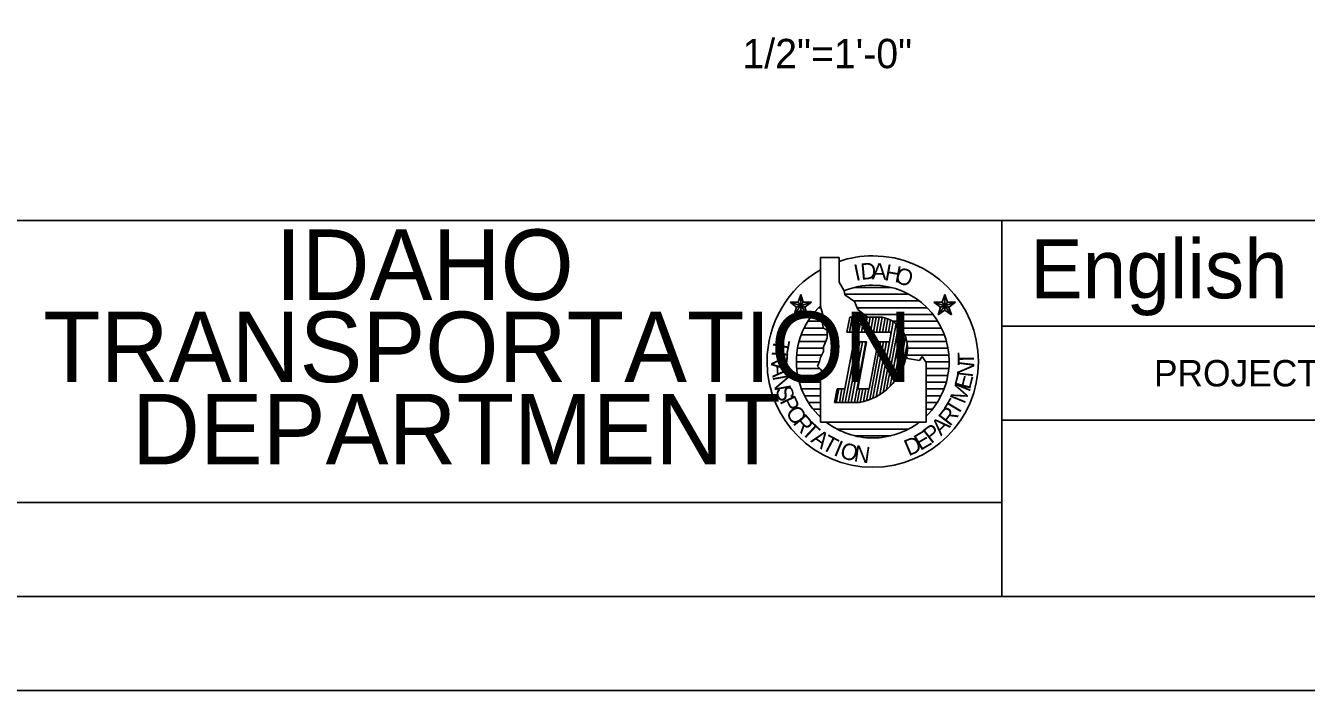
# Model space of a CAD drawing. Extents: x 0 to 68, y 0 to 47.1.
# Drawn here: x 28.11 to 41.74, y 0 to 7.08 of the extents above; entities that cross this region are included whole.
import ezdxf

# ---------------------------------------------------------------- set-up
doc = ezdxf.new("R2010")
doc.units = 0
for name, color, linetype in [('BORDER_ANNO_Cutsheet', 7, 'Continuous'), ('BRDG_ANNO_Anno-Sheet', 7, 'Continuous'), ('BRDG_ANNO_General-Notes', 7, 'Continuous')]:
    doc.layers.add(name, color=color, linetype=linetype)

msp = doc.modelspace()

# ---------------------------------------------------------------- linework, layer by layer
at = {"layer": 'BORDER_ANNO_Cutsheet'}
msp.add_lwpolyline([(0, 44), (68, 44), (68, 0), (0, 0)], close=True, dxfattribs=at)
at = {"layer": 'BRDG_ANNO_Anno-Sheet'}
for p, q in [((3, 5), (38.5, 5)), ((38.5, 1), (38.5, 5)), ((38.5, 5), (67, 5)), ((36.569, 4.085), (36.569, 4.606)), ((36.569, 4.606), (36.766, 4.606)), ((36.766, 4.346), (36.766, 4.606)), ((36.766, 4.346), (36.819, 4.252)), ((36.819, 4.252), (36.829, 4.21)), ((36.93, 4.289), (37.316, 4.289)), ((36.402, 4.08), (36.245, 4.131)), ((36.331, 4.131), (36.245, 4.131)), ((36.315, 4.08), (36.245, 4.131)), ((36.386, 4.131), (36.288, 3.996)), ((36.315, 4.08), (36.474, 4.131)), ((36.331, 4.131), (36.359, 4.214)), ((36.331, 4.131), (36.43, 3.996)), ((36.359, 4.047), (36.359, 4.214)), ((36.386, 4.131), (36.359, 4.214)), ((36.386, 4.131), (36.474, 4.131)), ((36.402, 4.08), (36.474, 4.131)), ((36.829, 4.21), (36.932, 4.138)), ((36.834, 4.216), (37.501, 4.216)), ((36.93, 4.145), (37.614, 4.145)), ((36.932, 4.138), (36.965, 4.054)), ((37.935, 4.08), (37.776, 4.131)), ((37.847, 4.08), (37.776, 4.131)), ((37.864, 4.131), (37.776, 4.131)), ((37.919, 4.131), (37.82, 3.996)), ((37.847, 4.08), (38.005, 4.131)), ((37.864, 4.131), (37.891, 4.214)), ((37.864, 4.131), (37.962, 3.996)), ((37.891, 4.047), (37.891, 4.214)), ((37.919, 4.131), (37.891, 4.214)), ((37.919, 4.131), (38.005, 4.131)), ((37.935, 4.08), (38.005, 4.131)), ((36.315, 4.08), (36.288, 3.996)), ((36.359, 4.047), (36.288, 3.996)), ((36.359, 4.047), (36.43, 3.996)), ((36.402, 4.08), (36.43, 3.996)), ((36.484, 4.001), (36.587, 4.001)), ((36.549, 4.072), (36.572, 4.072)), ((36.589, 4.013), (36.569, 4.085)), ((36.589, 3.95), (36.589, 4.013)), ((36.85, 3.814), (36.881, 3.971)), ((36.879, 3.814), (36.907, 3.971)), ((36.881, 3.971), (37.225, 3.971)), ((36.91, 3.814), (36.94, 3.971)), ((36.942, 3.814), (36.971, 3.971)), ((36.957, 4.072), (37.701, 4.072)), ((36.965, 4.054), (37.069, 3.971)), ((36.974, 3.814), (37.004, 3.971)), ((37.005, 3.814), (37.035, 3.971)), ((37.031, 4.001), (37.765, 4.001)), ((37.038, 3.814), (37.066, 3.971)), ((37.069, 3.814), (37.099, 3.971)), ((37.101, 3.814), (37.13, 3.971)), ((37.133, 3.814), (37.163, 3.971)), ((37.165, 3.814), (37.194, 3.971)), ((37.196, 3.814), (37.226, 3.971)), ((37.227, 3.814), (37.256, 3.962)), ((37.26, 3.814), (37.286, 3.954)), ((37.847, 4.08), (37.82, 3.996)), ((37.891, 4.047), (37.82, 3.996)), ((37.891, 4.047), (37.962, 3.996)), ((37.935, 4.08), (37.962, 3.996)), ((36.394, 3.856), (36.596, 3.856)), ((36.434, 3.929), (36.585, 3.929)), ((36.589, 3.897), (36.589, 3.95)), ((36.6, 3.856), (36.589, 3.897)), ((36.641, 3.835), (36.6, 3.856)), ((36.641, 3.782), (36.641, 3.835)), ((37.199, 3.149), (37.344, 3.924)), ((37.235, 3.171), (37.373, 3.904)), ((37.273, 3.201), (37.399, 3.877)), ((37.291, 3.814), (37.315, 3.94)), ((37.311, 3.237), (37.425, 3.849)), ((37.337, 3.929), (37.815, 3.929)), ((37.42, 3.856), (37.855, 3.856)), ((38.5, 3.875), (44.5, 3.875)), ((36.341, 3.712), (36.623, 3.712)), ((36.362, 3.785), (36.637, 3.785)), ((36.6, 3.657), (36.62, 3.7)), ((36.62, 3.7), (36.641, 3.751)), ((36.641, 3.751), (36.641, 3.782)), ((36.829, 3.21), (36.922, 3.71)), ((36.832, 3.064), (36.954, 3.71)), ((37.322, 3.814), (36.85, 3.814)), ((36.865, 3.064), (36.986, 3.71)), ((36.896, 3.064), (37.017, 3.71)), ((36.922, 3.71), (37.06, 3.71)), ((36.929, 3.064), (37.05, 3.71)), ((37.06, 3.71), (36.966, 3.21)), ((37.087, 3.21), (37.181, 3.71)), ((37.094, 3.095), (37.209, 3.71)), ((37.127, 3.11), (37.24, 3.71)), ((37.163, 3.126), (37.273, 3.71)), ((37.181, 3.71), (37.304, 3.71)), ((37.304, 3.71), (37.322, 3.814)), ((37.351, 3.28), (37.45, 3.812)), ((37.394, 3.337), (37.474, 3.764)), ((37.444, 3.435), (37.491, 3.69)), ((37.465, 3.785), (37.886, 3.785)), ((37.489, 3.712), (37.909, 3.712)), ((36.315, 3.569), (36.581, 3.569)), ((36.325, 3.641), (36.596, 3.641)), ((36.569, 3.544), (36.6, 3.606)), ((36.6, 3.606), (36.6, 3.657)), ((37.481, 3.555), (37.496, 3.532)), ((37.485, 3.569), (37.935, 3.569)), ((37.495, 3.641), (37.925, 3.641)), ((37.621, 3.512), (37.652, 3.554)), ((37.652, 3.554), (37.694, 3.491)), ((36.312, 3.496), (36.555, 3.496)), ((36.316, 3.425), (36.562, 3.425)), ((36.538, 3.45), (36.557, 3.501)), ((36.569, 3.419), (36.538, 3.45)), ((36.557, 3.501), (36.569, 3.544)), ((36.589, 3.387), (36.569, 3.419)), ((37.496, 3.532), (37.559, 3.522)), ((37.559, 3.522), (37.621, 3.512)), ((37.69, 3.496), (37.938, 3.496)), ((37.694, 3.491), (37.694, 2.855)), ((37.695, 3.425), (37.934, 3.425)), ((36.326, 3.353), (36.596, 3.353)), ((36.343, 3.281), (36.567, 3.281)), ((36.569, 3.304), (36.6, 3.335)), ((36.569, 2.855), (36.569, 3.304)), ((36.6, 3.366), (36.589, 3.387)), ((36.6, 3.335), (36.6, 3.366)), ((37.694, 3.353), (37.924, 3.353)), ((37.694, 3.281), (37.907, 3.281)), ((36.367, 3.209), (36.565, 3.209)), ((36.399, 3.136), (36.565, 3.136)), ((36.719, 3.064), (36.746, 3.21)), ((36.737, 3.064), (36.765, 3.21)), ((36.746, 3.21), (36.829, 3.21)), ((36.77, 3.064), (36.797, 3.21)), ((36.801, 3.064), (36.829, 3.21)), ((36.96, 3.064), (36.987, 3.21)), ((36.966, 3.21), (37.087, 3.21)), ((36.992, 3.065), (37.02, 3.21)), ((37.026, 3.074), (37.051, 3.21)), ((37.06, 3.084), (37.082, 3.21)), ((37.694, 3.209), (37.883, 3.209)), ((37.694, 3.136), (37.85, 3.136)), ((36.44, 3.065), (36.566, 3.065)), ((36.985, 3.064), (36.719, 3.064)), ((37.694, 3.065), (37.81, 3.065)), ((36.491, 2.992), (36.565, 2.992)), ((36.555, 2.921), (36.567, 2.921)), ((37.694, 2.992), (37.76, 2.992)), ((38.5, 2.875), (44.5, 2.875)), ((37.694, 2.855), (36.569, 2.855)), ((37.501, 2.782), (36.744, 2.782)), ((37.317, 2.711), (36.935, 2.711)), ((28, 2), (38.5, 2))]:
    msp.add_line(p, q, dxfattribs=at)
msp.add_lwpolyline([(3, 43), (67, 43), (67, 1), (3, 1)], close=True, dxfattribs=at)
for centre, radius, start, end in [((37.125, 3.5), 1.125, 90, 108.596), ((37.125, 3.5), 1.125, 0, 90), ((37.125, 3.5), 1.125, 119.6331, 180), ((37.125, 3.5), 0.813, 90, 112.1452), ((37.125, 3.5), 0.813, 0, 90), ((37.125, 3.5), 0.813, 133.1926, 180), ((37.167, 3.648), 0.328, 343.4981, 79.7362), ((36.87, 3.676), 0.623, 280.6479, 348.7719), ((37.125, 3.5), 1.125, 180, 270), ((37.125, 3.5), 0.813, 180.2644, 226.7946), ((37.125, 3.5), 1.125, 270, 0), ((37.125, 3.5), 0.813, 314.427, 0), ((37.125, 3.5), 0.813, 232.5658, 270), ((37.125, 3.5), 0.813, 270, 307.4536)]:
    msp.add_arc(centre, radius, start, end, dxfattribs=at)

# ---------------------------------------------------------------- texts
for s, height, p in [('IDAHO', 0.75, (30.767, 4.156)), ('English', 0.625, (38.801, 4.174)), ('TRANSPORTATION', 0.75, (28.294, 3.281)), ('PROJECT NO.', 0.28125, (40.118, 3.235)), ('DEPARTMENT', 0.75, (29.239, 2.406))]:
    msp.add_text(s, height=height, dxfattribs=at).set_placement(p)
for s, rotation, p in [('I', 11.9519, (36.944, 4.356)), ('D', 5.2118, (37.002, 4.369)), ('A', 357.8718, (37.114, 4.376)), ('H', 349.6318, (37.244, 4.367)), ('O', 342.1917, (37.349, 4.346)), ('T', 259.4265, (36.076, 3.751)), ('R', 266.0275, (36.053, 3.615)), ('T', 90.4926, (38.204, 3.459)), ('A', 273.764, (36.046, 3.481)), ('N', 83.1932, (38.19, 3.326)), ('N', 280.3758, (36.057, 3.342)), ('E', 75.6105, (38.159, 3.194)), ('S', 287.9279, (36.086, 3.208)), ('P', 295.4976, (36.131, 3.081)), ('M', 67.7139, (38.101, 3.041)), ('O', 302.6446, (36.191, 2.96)), ('R', 52.3344, (37.947, 2.802)), ('T', 59.0362, (38.027, 2.91)), ('R', 309.9079, (36.267, 2.845)), ('T', 317.1211, (36.355, 2.742)), ('A', 45, (37.851, 2.701)), ('A', 324.6375, (36.456, 2.651)), ('E', 30.5476, (37.631, 2.547)), ('P', 37.6656, (37.746, 2.619)), ('T', 331.7503, (36.569, 2.574)), ('I', 337.0213, (36.699, 2.507)), ('O', 343.3287, (36.765, 2.481)), ('N', 351.6598, (36.917, 2.44)), ('D', 22.9887, (37.506, 2.491))]:
    msp.add_text(s, height=0.174, rotation=rotation, dxfattribs=at).set_placement(p)
at = {"layer": 'BRDG_ANNO_General-Notes'}
msp.add_text('1/2"=1\'-0"', height=0.3125, dxfattribs=at).set_placement((35.738, 6.622))

doc.saveas('drawing.dxf')
